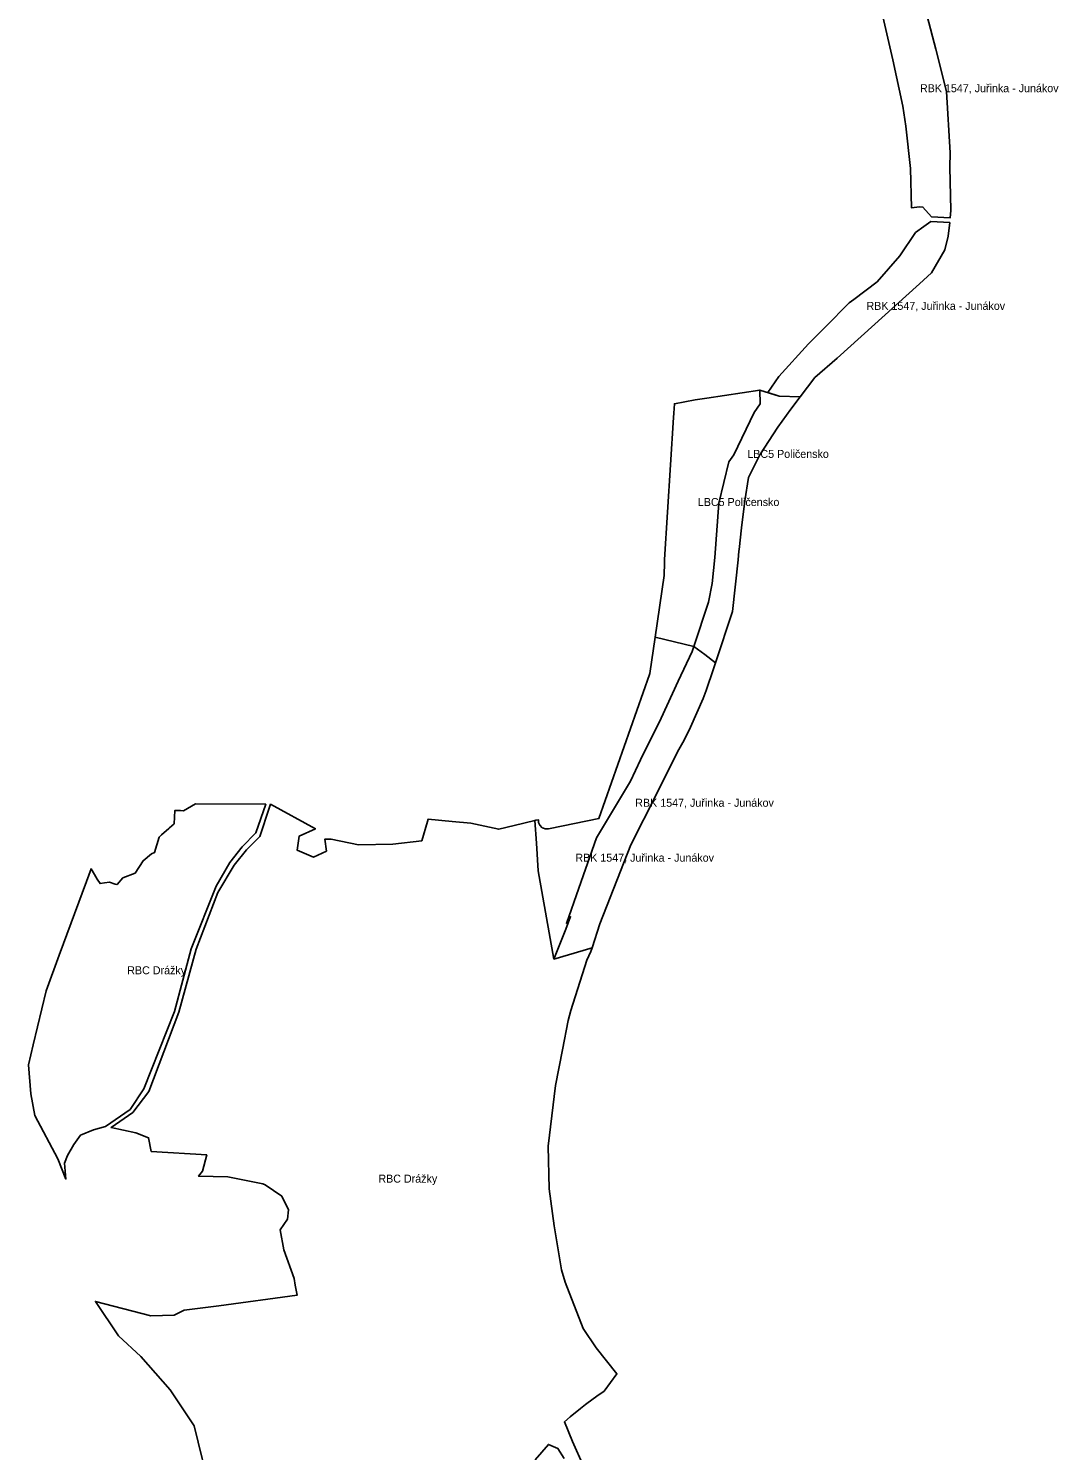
# Model space of a CAD drawing. Extents: x -502026 to -497556, y -1143322 to -1138019.
# Drawn here: x -498586 to -497556, y -1141900 to -1140479 of the extents above; entities that cross this region are included whole.
import ezdxf

# ---------------------------------------------------------------- set-up
doc = ezdxf.new("R2010")
doc.units = 0
for name, color, linetype in [('10', 7, 'Continuous'), ('13', 7, 'Continuous'), ('14', 7, 'Continuous'), ('16', 7, 'Continuous'), ('17', 7, 'Continuous')]:
    doc.layers.add(name, color=color, linetype=linetype)

msp = doc.modelspace()

# ---------------------------------------------------------------- linework, layer by layer
at = {"layer": '10'}
msp.add_lwpolyline([(-498508.726, -1141576.517), (-498520.882, -1141579.815), (-498533.648, -1141585.341), (-498540.508, -1141594.678), (-498546.605, -1141605.539), (-498549.654, -1141613.161), (-498548.259, -1141629.103), (-498556.46, -1141608.73), (-498579.41, -1141565.45), (-498583.42, -1141543.77), (-498585.78, -1141514.82), (-498581.03, -1141494.86), (-498568.18, -1141440.9), (-498555.09, -1141405.35), (-498527.91, -1141331.57), (-498523.26, -1141318.93), (-498519.76, -1141324.69), (-498516.97, -1141329.28), (-498514.23, -1141333.78), (-498509.74, -1141333.19), (-498504.81, -1141332.54), (-498499, -1141334.25), (-498497.12, -1141334.8), (-498491.38, -1141327.9), (-498479.25, -1141323.31), (-498471.24, -1141311.01), (-498462.88, -1141304.18), (-498459.83, -1141302.86), (-498455.25, -1141287.27), (-498452.88, -1141285.19), (-498445.49, -1141278.7), (-498444.72, -1141278.02), (-498440.25, -1141273.98), (-498439.39, -1141260.64), (-498433.91, -1141260.88), (-498430.71, -1141261.02), (-498418.71, -1141254.12), (-498348.596, -1141254.445), (-498358.52, -1141282.97), (-498372.17, -1141297.15), (-498384.43, -1141312.86), (-498398.03, -1141336.42), (-498423.24, -1141399.07), (-498439.71, -1141461.65), (-498470.47, -1141538.96), (-498484.13, -1141559.65)], close=True, dxfattribs=at)
for points in [[(-498403.77, -1141942.42), (-498420.03, -1141875.81), (-498444.04, -1141839.62), (-498473.4, -1141806.35), (-498495.69, -1141785.66), (-498518.8, -1141751.37), (-498463.46, -1141765.75), (-498440.19, -1141765.02), (-498430.11, -1141760.24), (-498395.541, -1141755.648), (-498317.26, -1141745.25), (-498319.11, -1141735.05), (-498320.36, -1141728.58), (-498330.58, -1141699.76), (-498334.06, -1141679.76), (-498327, -1141669.23), (-498325.9, -1141659.82), (-498332.54, -1141646.31), (-498349.26, -1141635.03), (-498351.49, -1141633.83), (-498386.55, -1141627.03), (-498415.78, -1141626.22), (-498411.73, -1141621.35), (-498407.52, -1141604.91), (-498463.01, -1141601.55), (-498465.718, -1141587.813), (-498478.577, -1141583.028), (-498503.245, -1141577.735), (-498481.37, -1141562.54), (-498465.58, -1141541.64), (-498435.49, -1141462.28), (-498418.05, -1141399.23), (-498396.49, -1141342.81), (-498380.22, -1141315.29), (-498367.96, -1141299.96), (-498354.69, -1141286.8), (-498344.82, -1141257.27), (-498343.818, -1141254.467), (-498299.02, -1141279.08), (-498315.12, -1141286.35), (-498317.15, -1141300.48), (-498300.97, -1141307.29), (-498287.94, -1141301.37), (-498289.435, -1141289.365), (-498287.32, -1141289.47), (-498283.26, -1141289.53), (-498255.91, -1141295.23), (-498221.71, -1141294.33), (-498192.64, -1141290.97), (-498187.01, -1141271.65), (-498186.41, -1141269.59), (-498162.39, -1141271.86), (-498143.69, -1141273.54), (-498115.7, -1141279.46), (-498100.31, -1141275.68), (-498079.54, -1141270.72), (-498078.06, -1141293.56), (-498076.29, -1141320.9), (-498060.66, -1141409.3), (-498046.11, -1141405.032), (-498022.382, -1141398.073), (-498023.58, -1141401.84), (-498027.82, -1141410.2), (-498043.69, -1141460.8), (-498046.55, -1141470.54), (-498052.15, -1141500), (-498058.92, -1141535.59), (-498066.45, -1141596.33), (-498065.44, -1141638.73), (-498060.4, -1141675.82), (-498053.14, -1141719.76), (-498049.24, -1141732.06), (-498031.51, -1141778.56), (-498018.34, -1141797.77), (-497997.74, -1141823.63), (-498010.44, -1141841.03), (-498017.71, -1141846.21), (-498022.83, -1141849.82), (-498027.83, -1141853.34), (-498029.01, -1141854.28), (-498034.07, -1141858.33), (-498044.28, -1141866.85), (-498050.16, -1141871.76), (-498041.9, -1141891.28), (-498020.05, -1141940.73)], [(-498050.26, -1141908.4), (-498056.61, -1141898.34), (-498066.06, -1141894.38), (-498079.32, -1141909.8)]]:
    msp.add_lwpolyline(points, dxfattribs=at)
at = {"layer": '13'}
for points in [[(-497664.79, -1140617.64), (-497663.84, -1140660.72), (-497663.83, -1140661.21), (-497664.59, -1140668.32), (-497683.37, -1140667.28), (-497691.84, -1140657.78), (-497695.17, -1140657.43), (-497703.28, -1140658.33), (-497704.11, -1140619.29), (-497708.97, -1140576.79), (-497712.04, -1140556.773), (-497722.062, -1140510.625), (-497736.978, -1140445.132), (-497738.975, -1140432.504), (-497710.808, -1140426.361), (-497697.403, -1140423.438), (-497687.61, -1140466.9), (-497679.11, -1140500), (-497668.31, -1140542.04), (-497664.47, -1140603.39)], [(-497814.604, -1140847.226), (-497835.62, -1140846.8), (-497846.86, -1140843.149), (-497835.81, -1140826.92), (-497806.18, -1140794.39), (-497789.21, -1140777.41), (-497765.45, -1140753.54), (-497760.824, -1140750.019), (-497737.64, -1140732.37), (-497714.85, -1140706.52), (-497699.12, -1140683.04), (-497690.827, -1140677.152), (-497683.84, -1140672.19), (-497665.12, -1140673.27), (-497666.55, -1140686.68), (-497670.07, -1140700.29), (-497683.21, -1140723.36), (-497695.22, -1140734.41), (-497777.39, -1140808.57), (-497799.97, -1140828.11)], [(-497983.66, -1141295.03), (-498014.69, -1141373.89), (-498022.382, -1141398.073), (-498046.11, -1141405.032), (-498060.66, -1141409.3), (-498048.79, -1141379.42), (-498043.93, -1141366.76), (-498048.14, -1141373.58), (-498035.73, -1141338.3), (-498018.11, -1141287.98), (-497983.96, -1141231.47), (-497974.01, -1141210.14), (-497953.58, -1141168.63), (-497936.6, -1141131.47), (-497922.56, -1141101.71), (-497920.923, -1141096.824), (-497909.86, -1141104.95), (-497899.159, -1141113.32), (-497903.42, -1141126.29), (-497906.06, -1141133.81), (-497908.5, -1141141), (-497911.36, -1141148.73), (-497924.16, -1141177.53), (-497930.44, -1141190.51), (-497937.08, -1141202.15), (-497958.04, -1141244.5)]]:
    msp.add_lwpolyline(points, close=True, dxfattribs=at)
at = {"layer": '14'}
msp.add_lwpolyline([(-497920.923, -1141096.824), (-497922.56, -1141101.71), (-497936.6, -1141131.47), (-497953.58, -1141168.63), (-497974.01, -1141210.14), (-497983.96, -1141231.47), (-498018.11, -1141287.98), (-498035.73, -1141338.3), (-498048.14, -1141373.58), (-498043.93, -1141366.76), (-498048.79, -1141379.42), (-498060.66, -1141409.3), (-498076.29, -1141320.9), (-498078.06, -1141293.56), (-498079.54, -1141270.72), (-498078.55, -1141270.48), (-498075.921, -1141270.104), (-498075.895, -1141272.009), (-498075.885, -1141272.726), (-498074.707, -1141275.584), (-498072.345, -1141277.955), (-498070.925, -1141278.52), (-498069.236, -1141279.192), (-498066.144, -1141279.148), (-498064.477, -1141278.806), (-498015.675, -1141268.789), (-497965.056, -1141124.761), (-497964.714, -1141123.789), (-497959.442, -1141087.571)], close=True, dxfattribs=at)
at = {"layer": '16'}
msp.add_lwpolyline([(-497882.24, -1141061.82), (-497899.159, -1141113.32), (-497909.86, -1141104.95), (-497920.923, -1141096.824), (-497906.09, -1141052.54), (-497902.6, -1141034.05), (-497899.9, -1141008.04), (-497895.94, -1140953.5), (-497885.67, -1140912.21), (-497880.69, -1140905.18), (-497860.49, -1140863.16), (-497854.48, -1140854.34), (-497854.86, -1140840.55), (-497835.62, -1140846.8), (-497814.604, -1140847.226), (-497824, -1140859.5), (-497836.97, -1140877.6), (-497854.91, -1140905.15), (-497866.12, -1140928.06), (-497869.81, -1140951.44), (-497873.17, -1140978.35), (-497875.52, -1141000), (-497875.68, -1141001.48), (-497876.63, -1141010.16)], close=True, dxfattribs=at)
at = {"layer": '17'}
msp.add_lwpolyline([(-497906.09, -1141052.54), (-497920.923, -1141096.824), (-497959.442, -1141087.571), (-497950.453, -1141025.823), (-497950.085, -1141012.957), (-497950, -1141010), (-497941.059, -1140868.085), (-497940.79, -1140863.814), (-497940.12, -1140854.25), (-497919.46, -1140850.42), (-497907.84, -1140848.72), (-497854.86, -1140840.55), (-497854.48, -1140854.34), (-497860.49, -1140863.16), (-497880.69, -1140905.18), (-497885.67, -1140912.21), (-497895.94, -1140953.5), (-497899.9, -1141008.04), (-497902.6, -1141034.05)], close=True, dxfattribs=at)

# ---------------------------------------------------------------- texts
at = {"layer": '10'}
for p in [(-498487.06, -1141424.447), (-498236.069, -1141632.685)]:
    msp.add_text('RBC Drážky', height=8, dxfattribs=at).set_placement(p)
at = {"layer": '13'}
for p in [(-497694.812, -1140542.898), (-497748.27, -1140760.413), (-497979.362, -1141257.022)]:
    msp.add_text('RBK 1547, Juřinka - Junákov', height=8, dxfattribs=at).set_placement(p)
at = {"layer": '14'}
msp.add_text('RBK 1547, Juřinka - Junákov', height=8, dxfattribs=at).set_placement((-498039.199, -1141311.931))
at = {"layer": '16'}
msp.add_text('LBC5 Poličensko', height=8, dxfattribs=at).set_placement((-497867.346, -1140908.378))
at = {"layer": '17'}
msp.add_text('LBC5 Poličensko', height=8, dxfattribs=at).set_placement((-497916.798, -1140956.458))

doc.saveas('drawing.dxf')
